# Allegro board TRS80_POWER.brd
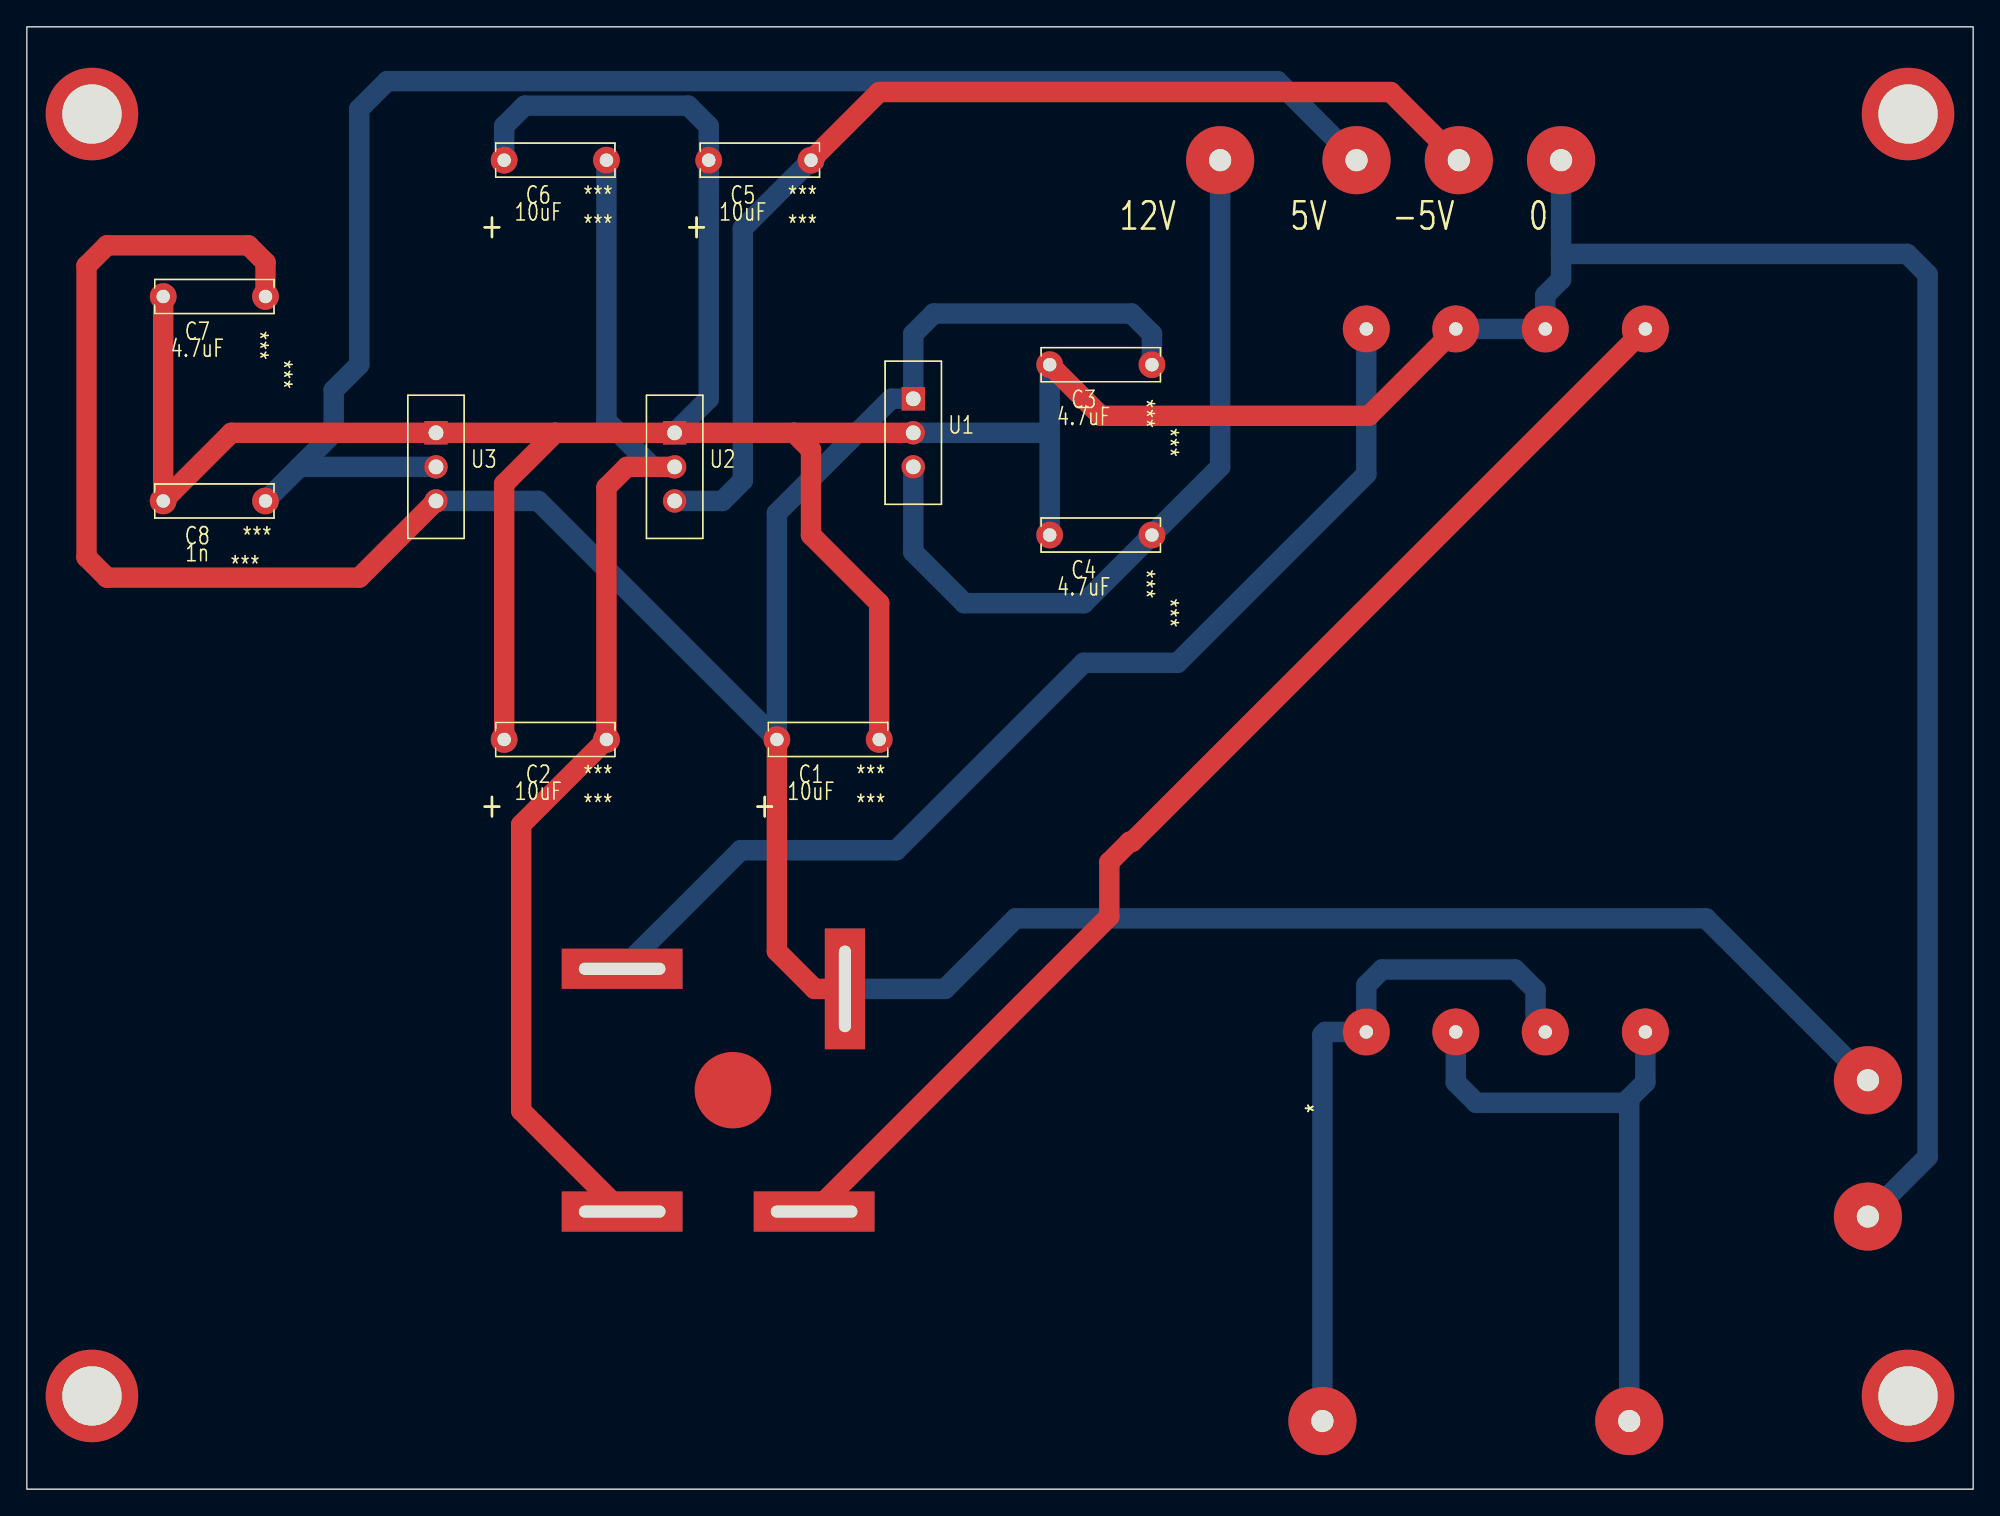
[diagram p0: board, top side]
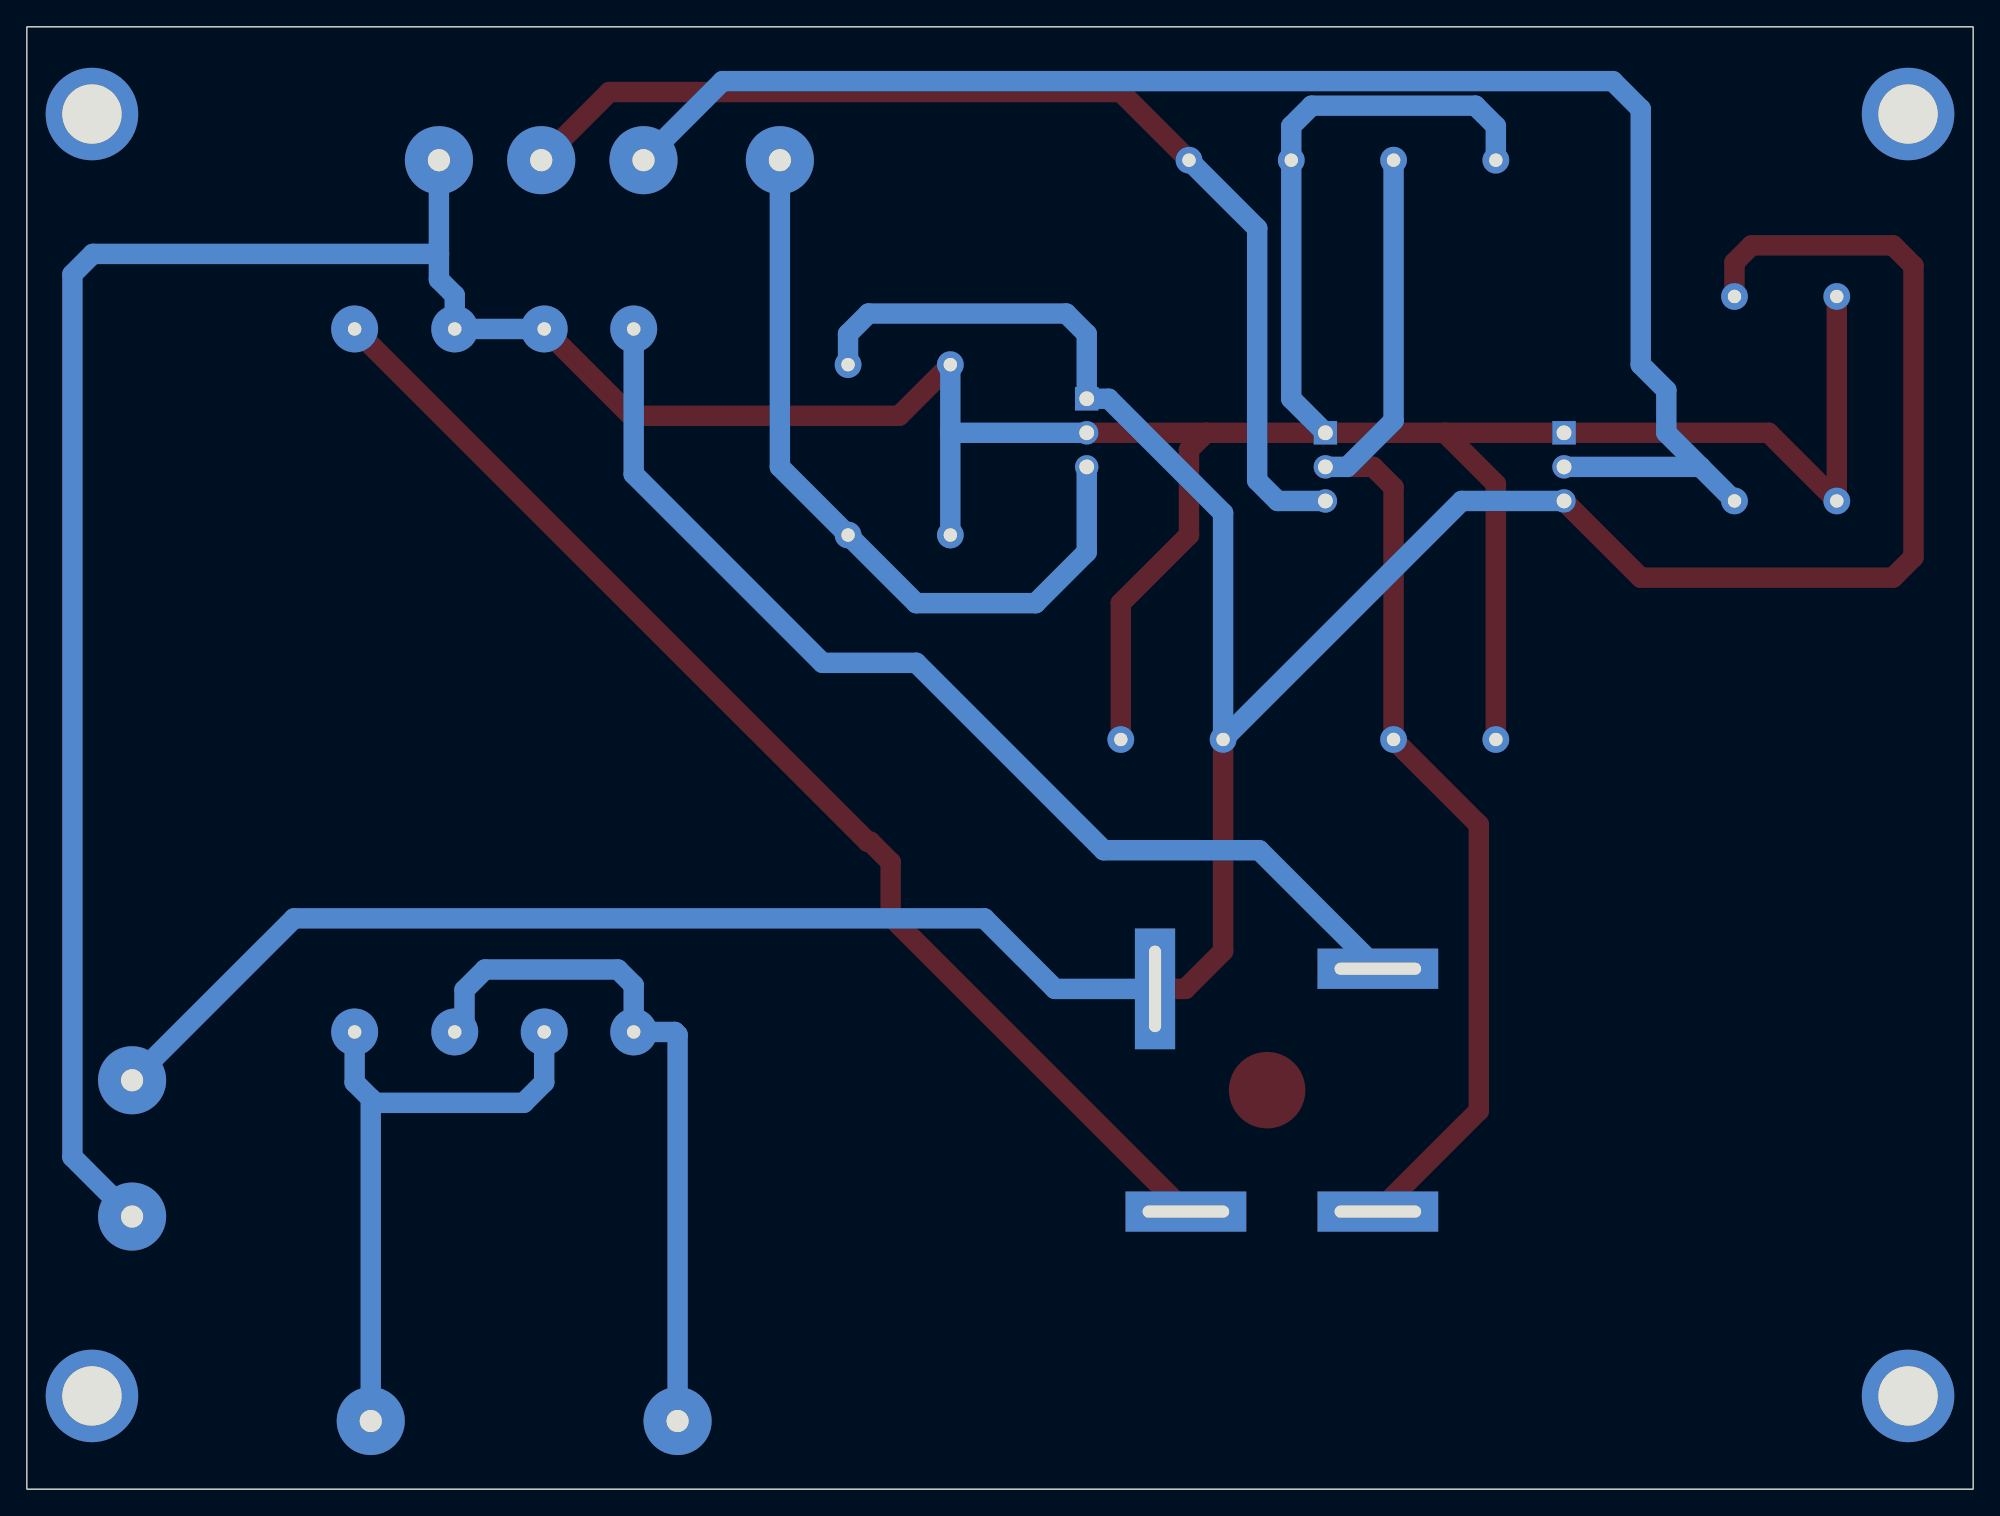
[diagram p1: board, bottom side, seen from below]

Outline 145 x 109 mm; copper layers: TOP, BOTTOM. Coordinates in mm from the lower left corner of the outline.
Outline path: rectangle 0,0 145,109

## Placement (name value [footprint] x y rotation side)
BR1  -  [MB354-BP]  38.1 15.24 0 top
C1  10uF  [POLCAP300]  55.88 55.88 0 top
C2  10uF  [POLCAP300]  35.56 55.88 0 top
C3  4.7uF  [CAP300]  76.2 83.82 0 top
C4  4.7uF  [CAP300]  76.2 71.12 0 top
C5  10uF  [POLCAP300]  50.8 99.06 0 top
C6  10uF  [POLCAP300]  35.56 99.06 0 top
C7  4.7uF  [CAP300]  10.16 88.9 0 top
C8  1n  [CAP300]  10.16 73.66 0 top
J1  CON1  [18AWG_HOLE]  137.16 30.48 0 top
J2  CON1  [18AWG_HOLE]  137.16 20.32 0 top
J3  CON1  [18AWG_HOLE]  119.38 5.08 0 top
J4  CON1  [18AWG_HOLE]  96.52 5.08 0 top
J5  CON1  [18AWG_HOLE]  88.9 99.06 0 top
J6  CON1  [18AWG_HOLE]  99.06 99.06 0 top
J7  CON1  [18AWG_HOLE]  106.68 99.06 0 top
J8  CON1  [18AWG_HOLE]  114.3 99.06 0 top
NOREF  -  [unnamed]  140.15 102.5 0 top
NOREF#2  -  [unnamed]  4.85 102.5 0 top
NOREF#3  -  [unnamed]  140.15 6.95 0 top
NOREF#4  -  [unnamed]  4.85 6.95 0 top
TR1  10:1 24VA Transformer  [DPC-40-600]  132.08 30.48 90 top
U1  lm7812act 12v reg.  [LM7812ACT]  66.04 78.74 0 top
U2  LM7905CT -5V Regulator  [LM7812ACT]  48.26 76.2 0 top
U3  Diodes_AP1117T50L-U  [LM7812ACT]  30.48 76.2 0 top

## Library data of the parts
BR1 = MB354-BP
C1 C2 C5 C6 = C_elect: Tolerance: ***; User Part Number: ***
C3 C4 C7 C8 = C: Tolerance: ***; User Part Number: ***
J1-J8 = CON1
TR1 = dpc-40-600 xfmr 24va
U1 = lm7812act 12v reg.
U2 = LM7905CT -5V Regulator
U3 = Diodes_AP1117T50L-U

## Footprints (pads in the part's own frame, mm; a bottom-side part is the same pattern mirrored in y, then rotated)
18AWG_HOLE
  round 5.08 hole 1.651: 1(0,0)
CAP300
  round 2 hole 1: 1(0,0) 2(7.62,0)
DPC-40-600
  round 3.5 hole 1: 1(3.6,11.5) 2(3.6,18.957) 3(3.6,25.623) 4(3.6,32.29) 5(56,11.5) 6(56,18.957) 7(56,25.623) 8(56,32.29)
LM7812ACT
  rect 1.75x1.75 hole 1.1: 1(0,2.54)
  round 1.75 hole 1.1: 2(0,0) 3(0,-2.54)
MB354-BP
  round 5.7 smd: (14.5,14.5)
  rect 3x9 hole 0.9x6.45: 1(22.85,22.05)
  rect 9x3 hole 6.45x0.9: 2(20.55,5.45) 3(6.25,5.45) 4(6.25,23.55)
POLCAP300
  round 2 hole 1: N(7.62,0) P(0,0)
unnamed
  round 6.9 hole 4.42: (0,0)

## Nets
12V AC: BR1.2(AC1) TR1.5
12V_UNREG: BR1.1(DC+) C1.P(+) C3.2 C7.2 J1.1 U1.1(IN) U3.3(VIN)
120V AC MAINS: J3.1 TR1.1 TR1.3
-12V_UNREG: BR1.3(DC-) C2.N(-) C6.N(-) U2.2(IN)
V5: C8.2 J6.1 U3.2(VOUT)
V12: C4.2 J5.1 U1.3(OUT)
0: C1.N(-) C2.P(+) C3.1 C4.1 C5.P(+) C6.P(+) C7.1 C8.1 J2.1 J8.1 TR1.6 TR1.7 U1.2(GND) U2.1(GND) U3.1(GND)
V-5: C5.N(-) J7.1 U2.3(OUT)
N00330: J4.1 TR1.2 TR1.4
N00450: BR1.4(AC2) TR1.8

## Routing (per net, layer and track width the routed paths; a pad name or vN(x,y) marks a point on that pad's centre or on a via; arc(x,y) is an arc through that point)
12V AC: length 91.6
  TOP w1.524: TR1.5 82.36,48.26 82.17,48.26 80.64,46.74 80.64,42.69 BR1.2
12V_UNREG: length 262.7
  TOP w1.524: C7.2 17.78,91.44 16.51,92.71 5.97,92.71 4.45,91.19 4.45,69.47 5.97,67.94 24.77,67.94 U3.3 ; C1.P 55.88,40.1 58.69,37.29 BR1.1
  BOTTOM w1.524: C3.2 83.82,86.11 82.3,87.63 67.56,87.63 66.04,86.11 U1.1 64.4,81.28 55.88,72.76 C1.P 38.1,73.66 U3.3 ; J1.1 125.09,42.55 73.66,42.55 68.4,37.29 BR1.1
120V AC MAINS: length 46.9
  BOTTOM w1.524: 119.38,29.12 120.58,30.32 TR1.1 ; 119.38,29.12 119.06,28.8 107.98,28.8 106.46,30.32 TR1.3 ; 119.38,29.12 J3.1
-12V_UNREG: length 91.4
  TOP w1.524: U2.2 44.7,76.2 43.18,74.68 C2.N 36.83,49.53 36.83,28.21 BR1.3
  BOTTOM w1.524: U2.2 46.62,76.2 43.18,79.64 C6.N
V5: length 119.9
  BOTTOM w1.524: J6.1 93.17,104.95 26.85,104.95 24.77,102.87 24.77,83.82 22.86,81.92 22.86,78.74 20.32,76.2 ; 20.32,76.2 U3.2 ; 20.32,76.2 C8.2
V12: length 57.9
  BOTTOM w1.524: U1.3 66.04,69.85 69.85,66.04 78.74,66.04 C4.2 88.9,76.2 J5.1
0: length 343.2
  TOP w1.524: C1.N 63.5,66.04 58.42,71.12 58.42,77.47 57.15,78.74 ; C7.1 C8.1 15.24,78.74 U3.1 39.37,78.74 ; 57.15,78.74 U1.2 ; 57.15,78.74 U2.1 39.37,78.74 ; TR1.7 99.99,80.01 80.01,80.01 C3.1 ; C2.P 35.56,74.93 39.37,78.74
  BOTTOM w1.524: 114.3,92.08 114.3,90.17 113.12,88.99 TR1.6 TR1.7 ; 114.3,92.08 J8.1 ; 114.3,92.08 140.08,92.08 141.6,90.55 141.6,24.77 J2.1 ; U2.1 50.8,81.28 C5.P 50.8,101.6 49.28,103.12 37.08,103.12 35.56,101.6 C6.P ; 76.2,78.74 C4.1 ; 76.2,78.74 C3.1 ; 76.2,78.74 U1.2
V-5: length 84.2
  TOP w1.524: J7.1 101.6,104.14 63.5,104.14 C5.N
  BOTTOM w1.524: C5.N 53.34,93.98 53.34,75.18 51.82,73.66 U2.3
N00330: length 52.8
  BOTTOM w1.524: TR1.2 112.39,34.81 112.39,37.21 110.87,38.73 100.97,38.73 99.79,37.56 TR1.4 96.73,34.08 96.52,33.87 J4.1
N00450: length 81.5
  BOTTOM w1.524: BR1.4 53.19,47.62 64.77,47.62 78.74,61.59 85.72,61.59 99.79,75.66 TR1.8

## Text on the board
Ref Des/Silkscreen Top: 12V | 5V | -5V | 0
